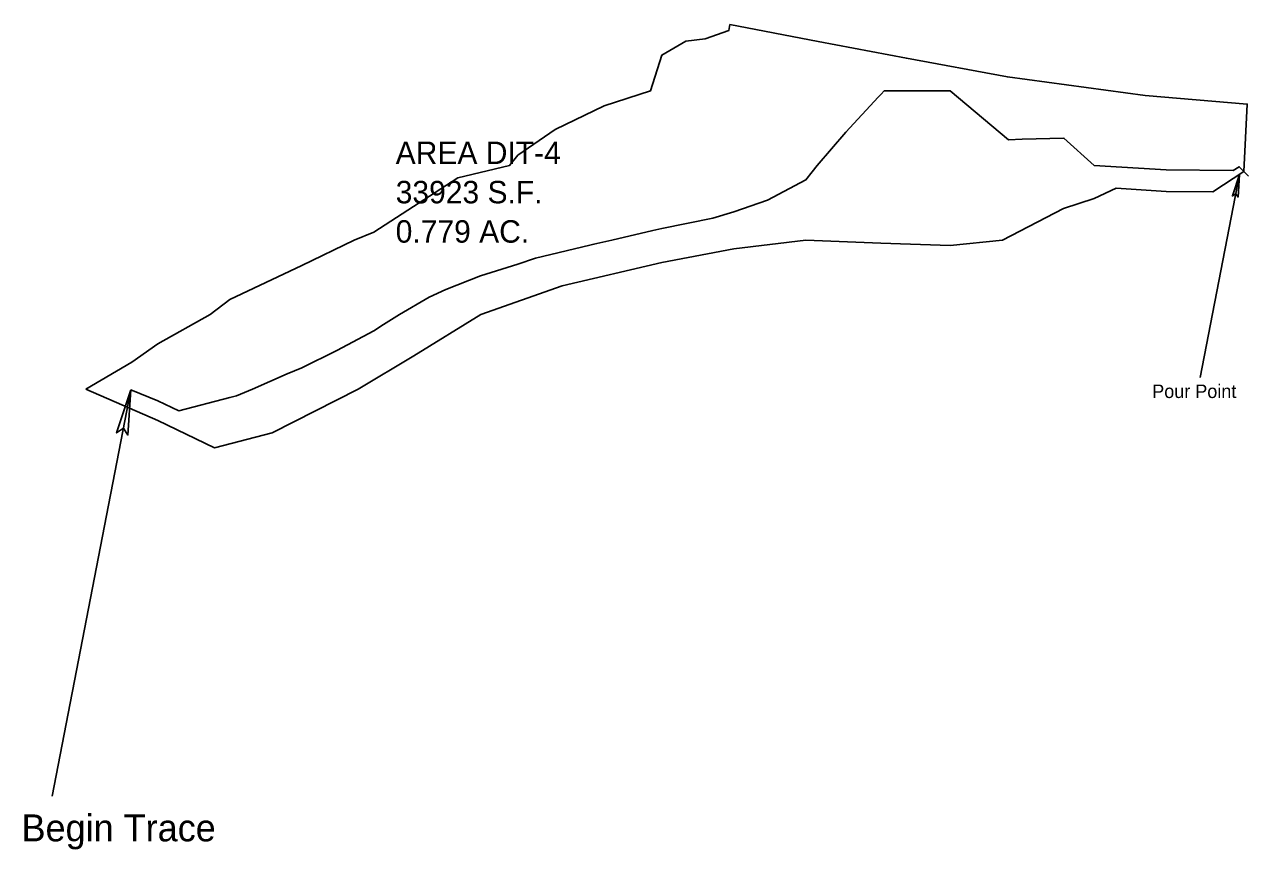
# Model space of a CAD drawing. Extents: x 3333 to 5445, y 2661 to 3371.
import ezdxf

# ---------------------------------------------------------------- set-up
doc = ezdxf.new("R2010")
doc.units = 0
for name, color, linetype in [('DESIGN - SCRATCH - User 1', 7, 'Continuous'), ('SURVEY - CENTERLINE - Preliminary', 7, 'Continuous'), ('SURVEY - CENTERLINE - Preliminary Text', 7, 'Continuous'), ('SURVEY - DRAINAGE - Area Shapes', 7, 'Continuous')]:
    doc.layers.add(name, color=color, linetype=linetype)

msp = doc.modelspace()

# ---------------------------------------------------------------- linework, layer by layer
at = {"layer": 'DESIGN - SCRATCH - User 1'}
msp.add_line((3874.61, 2961.55), (3857.08, 2871.1), dxfattribs=at)
msp.add_lwpolyline([(3874.61, 2961.55), (3873.93, 2951.44), (3872.95, 2952.96), (3871.42, 2951.93)], close=True, dxfattribs=at)
msp.add_lwpolyline([(3874.61, 2961.55), (3873.93, 2951.44), (3872.95, 2952.96), (3871.42, 2951.93), (3874.61, 2961.55)], dxfattribs=at)
at = {"layer": 'SURVEY - CENTERLINE - Preliminary'}
msp.add_lwpolyline([(3380.79, 2865.7), (3392.78, 2860.77), (3402.09, 2856.31), (3424.85, 2862.23), (3427.74, 2862.96), (3434.87, 2865.94), (3450.36, 2872.74), (3456.93, 2875.44), (3472.43, 2883.09), (3489.01, 2891.98), (3493.29, 2894.7), (3500.4, 2899.13), (3513.64, 2906.83), (3521.08, 2910.34), (3536.44, 2916.43), (3553.16, 2921.59), (3560.98, 2924.23), (3585.24, 2930.07), (3587.02, 2930.47), (3595.01, 2932.32), (3613.26, 2936.51), (3617.32, 2937.39), (3639.96, 2942.08), (3649.39, 2944.85), (3664.35, 2950.03), (3681.47, 2959.08), (3684.15, 2962.73), (3686.52, 2965.51), (3699.23, 2980.32), (3713.55, 2995.87), (3714.91, 2997.28), (3716.24, 2998.69), (3745.62, 2998.69), (3771.67, 2976.96), (3777.7, 2977.24), (3796.35, 2977.69), (3809.78, 2965.51), (3841.85, 2963.53), (3871.74, 2963.24), (3874.44, 2964.98), (3878.58, 2960.69)], dxfattribs=at)
at = {"layer": 'SURVEY - CENTERLINE - Preliminary Text'}
msp.add_line((3380.79, 2865.7), (3345.73, 2684.8), dxfattribs=at)
msp.add_lwpolyline([(3380.79, 2865.7), (3379.42, 2845.49), (3377.46, 2848.52), (3374.41, 2846.46)], close=True, dxfattribs=at)
msp.add_lwpolyline([(3380.79, 2865.7), (3379.42, 2845.49), (3377.46, 2848.52), (3374.41, 2846.46), (3380.79, 2865.7)], dxfattribs=at)
at = {"layer": 'SURVEY - DRAINAGE - Area Shapes'}
for points in [[(3647.55, 3028.27), (3647.15, 3025.66), (3636.51, 3021.95), (3627.93, 3020.9), (3617.32, 3014.67), (3612.25, 2998.69), (3591.6, 2992.11), (3569.79, 2981.49), (3553.16, 2970.05), (3549.42, 2965.51), (3526.44, 2959.96), (3489.01, 2935.87), (3480.18, 2932.32), (3456.93, 2921.01), (3424.85, 2905.84), (3416.09, 2899.13), (3392.78, 2886.19), (3381.23, 2877.89), (3360.7, 2865.94)], [(3360.7, 2865.94), (3392.78, 2851.92), (3417.99, 2839.86), (3443.71, 2846.43), (3482.01, 2865.94), (3506.77, 2880.76), (3536.61, 2899.13), (3572.85, 2911.94), (3617.32, 2922.29), (3649.39, 2928.43), (3681.47, 2932.32), (3714.85, 2930.97), (3745.62, 2929.84), (3768.95, 2932.32), (3796.22, 2946.35), (3809.78, 2950.82), (3819.57, 2955.38), (3841.85, 2954), (3862.62, 2953.8), (3876.55, 2962.8), (3878, 2992.86), (3832.57, 2996.61), (3771.22, 3004.92), (3726.19, 3013.22), (3686.9, 3020.73), (3647.55, 3028.27)]]:
    msp.add_lwpolyline(points, dxfattribs=at)

# ---------------------------------------------------------------- texts
at = {"layer": 'DESIGN - SCRATCH - User 1'}
msp.add_text('Pour Point', height=6, dxfattribs=at).set_placement((3835.69, 2862))
at = {"layer": 'SURVEY - CENTERLINE - Preliminary Text'}
msp.add_text('Begin Trace', height=12, dxfattribs=at).set_placement((3332.05, 2664.65))
at = {"layer": 'SURVEY - DRAINAGE - Area Shapes'}
for s, p in [('AREA DIT-4', (3498.71, 2966.15)), ('33923 S.F.', (3498.71, 2948.65)), ('0.779 AC.', (3498.71, 2931.15))]:
    msp.add_text(s, height=10, dxfattribs=at).set_placement(p)

doc.saveas('drawing.dxf')
